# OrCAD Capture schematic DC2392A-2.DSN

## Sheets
1 PAGE2: size A; title: HIGH VOLTAGE SWITCHING SURGE STOPPER; rev: 2; company: TM
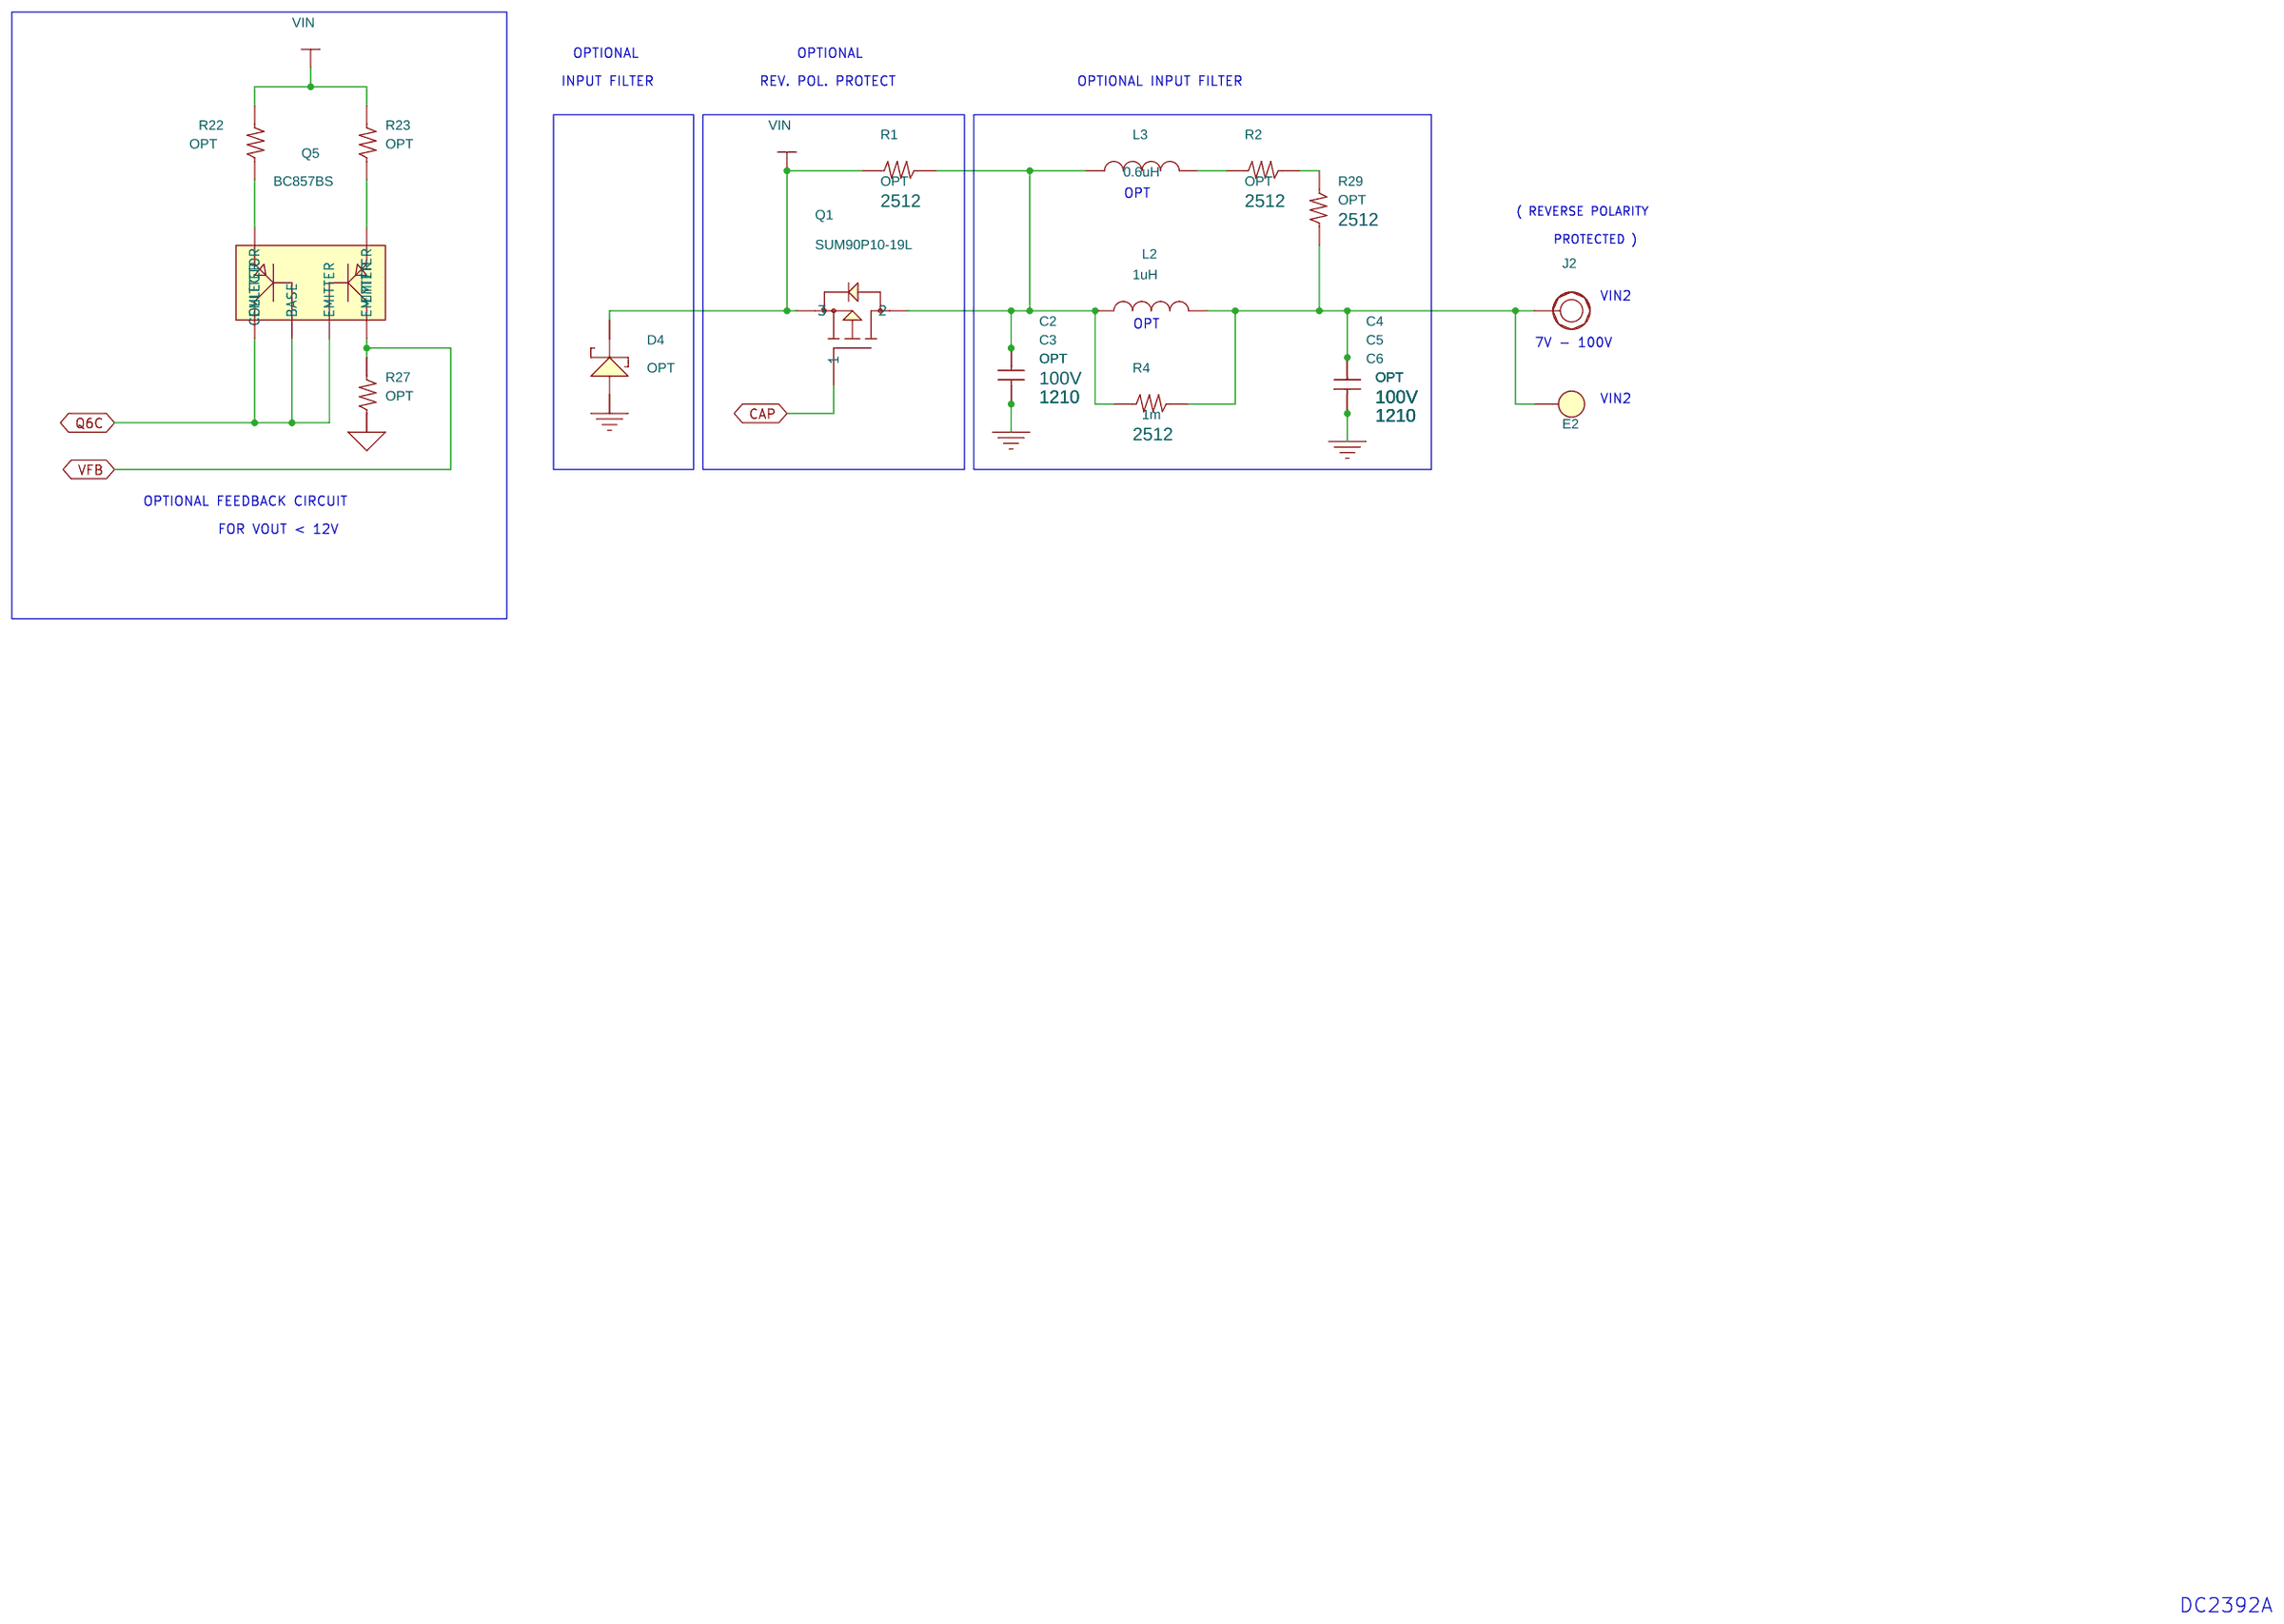
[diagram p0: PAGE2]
2 LTC7860EMSE: size Custom
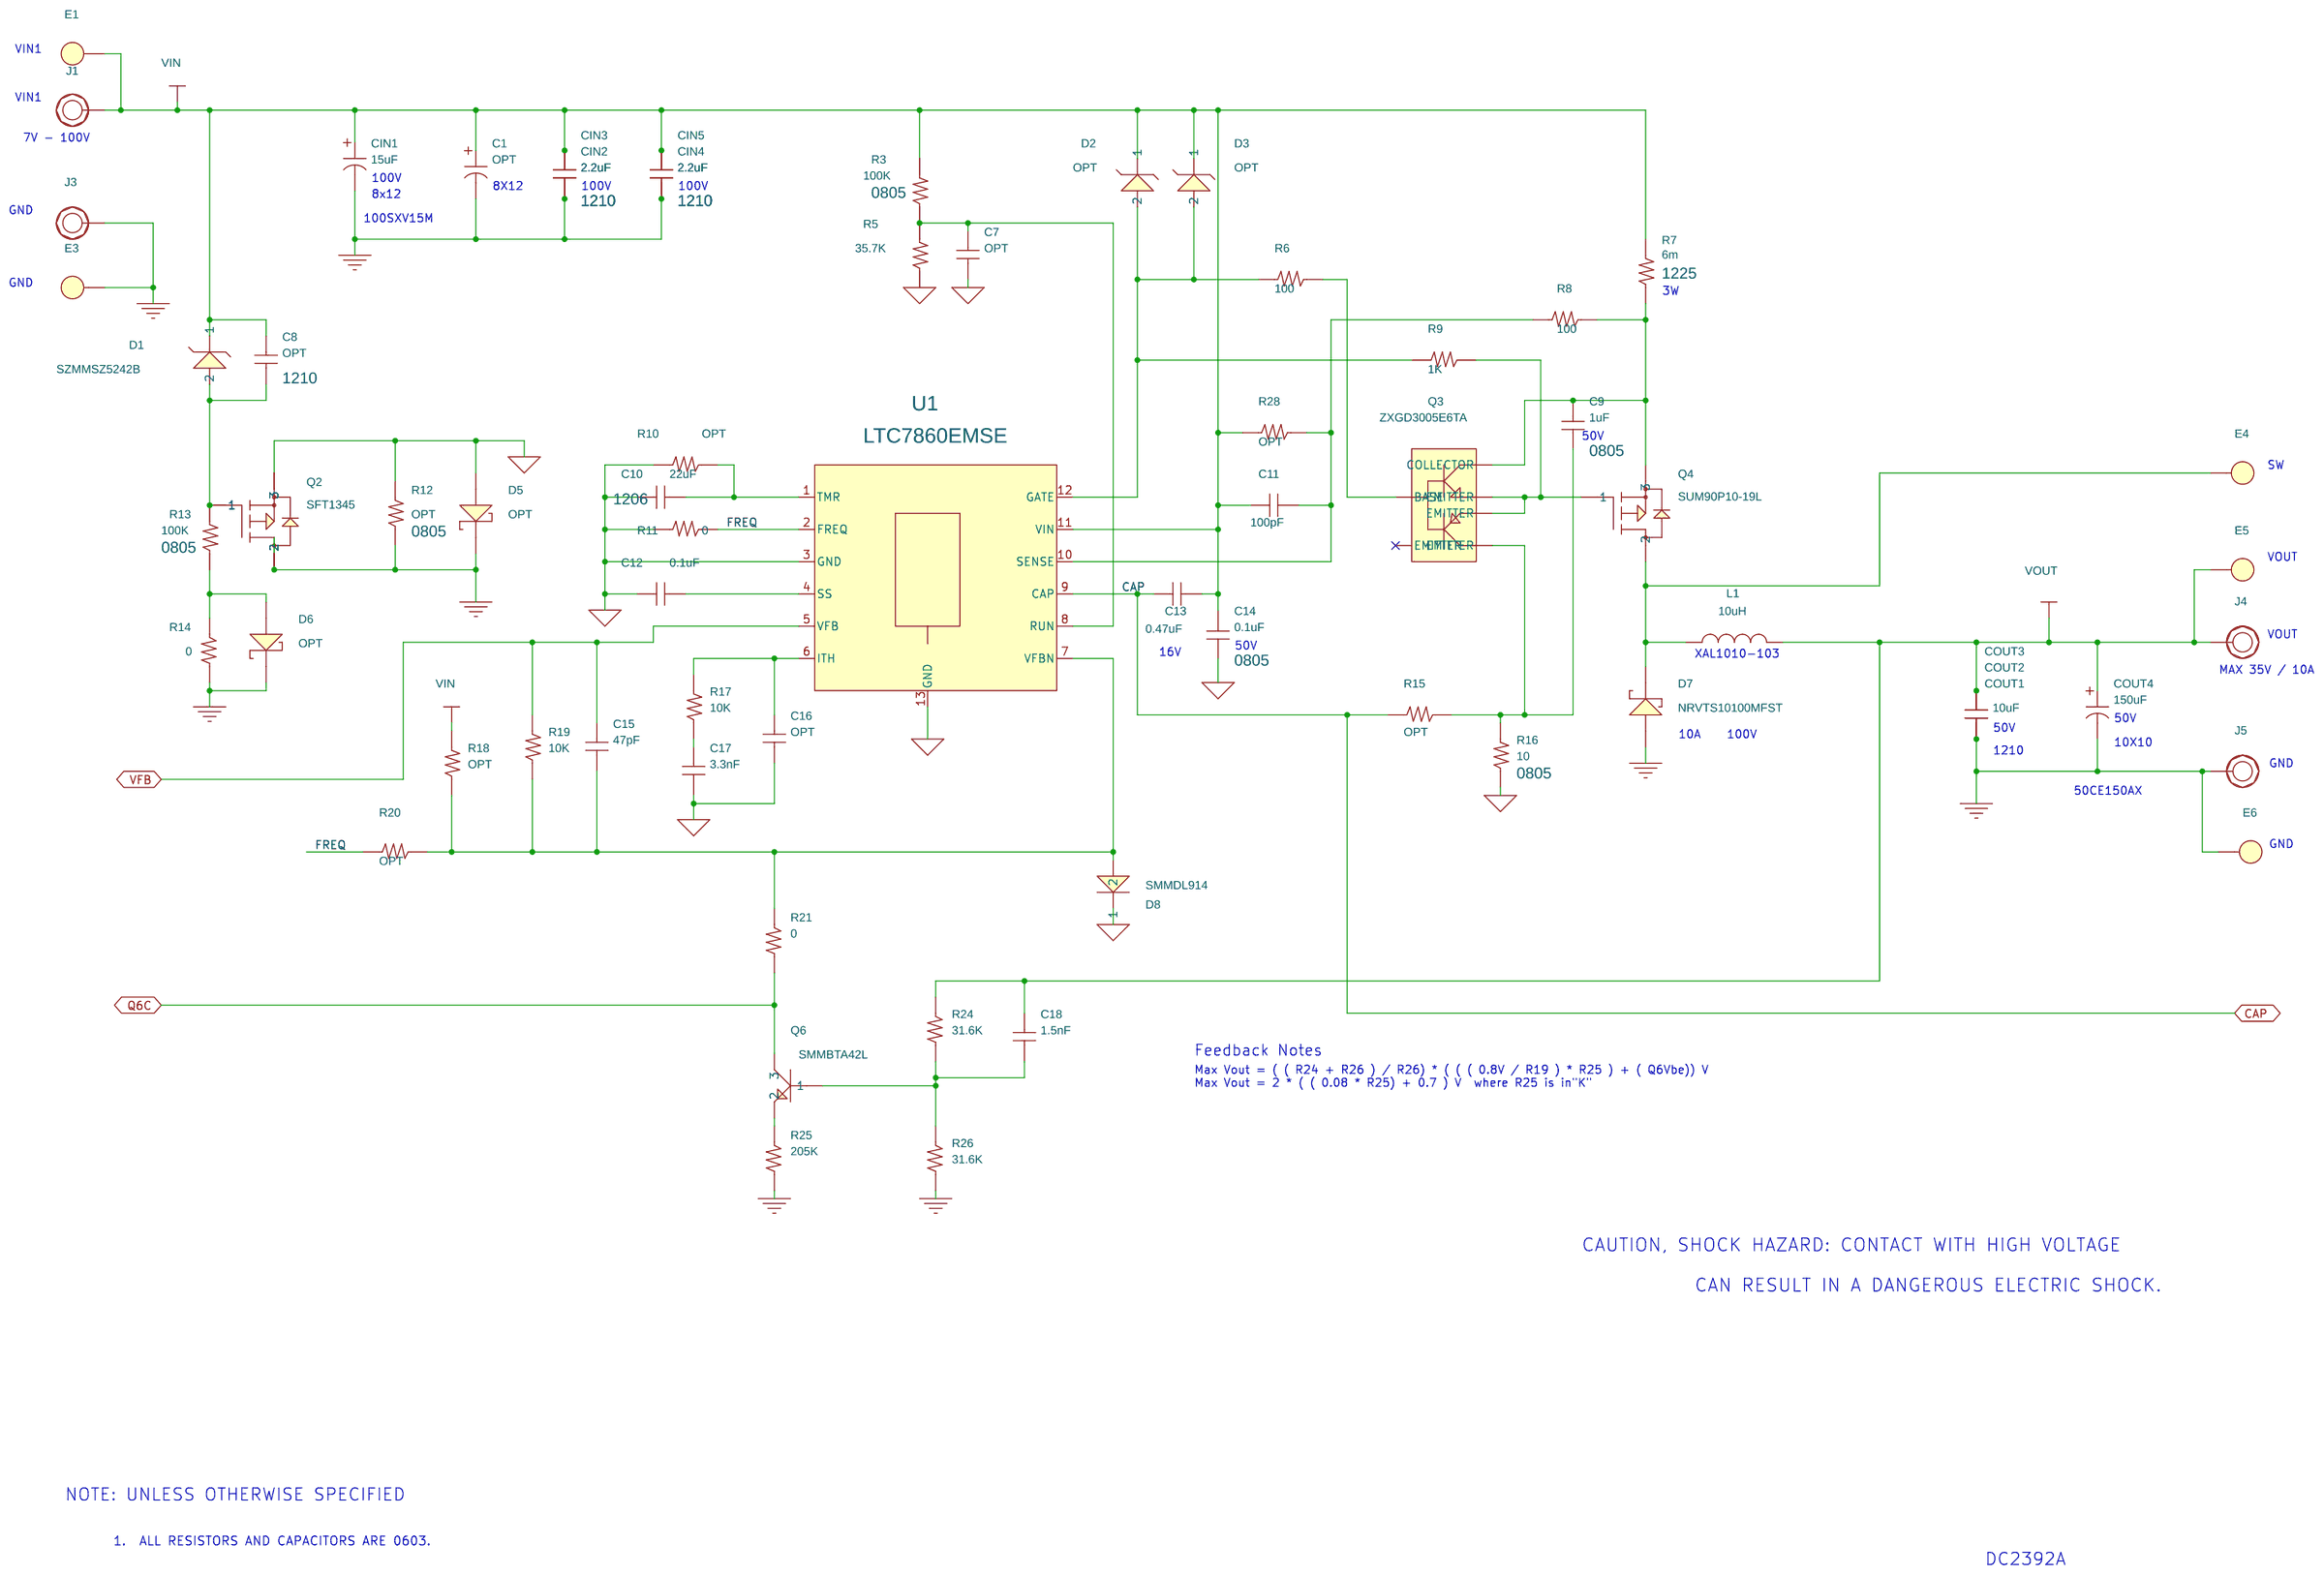
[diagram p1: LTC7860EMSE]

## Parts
sheet LTC7860EMSE
C1  OPT  [CAP-E12-8X12]
C7  OPT  [0603]
C8  OPT  [1210]
C9  1uF  [0805]
C10  22uF  [1206]
C11  100pF  [0603]
C12  0.1uF  [0603]
C13  0.47uF  [0603]
C14  0.1uF  [0805]
C15  47pF  [0603]
C16  OPT  [0603]
C17  3.3nF  [0603]
C18  1.5nF  [0603]
CIN1  15uF  [CAP-E12-8X12]
CIN2  2.2uF  [1210]
CIN3  2.2uF  [1210]
CIN4  2.2uF  [1210]
CIN5  2.2uF  [1210]
COUT1  10uF  [1206]
COUT2  10uF  [1206]
COUT3  10uF  [1206]
COUT4  150uF  [C-HVH-10X10.5]
D1  SZMMSZ5242B  [SOD123]
D2  OPT  [SOD123]
D3  OPT  [SOD123]
D5  OPT  [SOD123]
D6  OPT  [SOD323]
D7  NRVTS10100MFST  [DFN5-SO-8FL]
D8  SMMDL914  [SOD323]
E1  E_0  [TP\MMX\2501-2]
E3  E_0  [TP\MMX\2501-2]
E4  E_0  [TP\MMX\2501-2]
E5  E_0  [TP\MMX\2501-2]
E6  E_0  [TP\MMX\2501-2]
J1  Banana Jack  [KEYSTONE-575-4]
J3  Banana Jack  [KEYSTONE-575-4]
J4  Banana Jack  [KEYSTONE-575-4]
J5  Banana Jack  [KEYSTONE-575-4]
L1  10uH  [IND-XAL1010-103ME]
Q2  SFT1345  [TO-252]
Q3  ZXGD3005E6TA  [SOT23-6]
Q4  SUM90P10-19L  [TO-263AB]
Q6  SMMBTA42L  [SOT23]
R3  100K  [0805]
R5  35.7K  [0603]
R6  100  [0603]
R7  6m  [1225]
R8  100  [0603]
R9  1K  [0603]
R10  OPT  [0603]
R11  0  [0603]
R12  OPT  [0805]
R13  100K  [0805]
R14  0  [0603]
R15  OPT  [0603]
R16  10  [0805]
R17  10K  [0603]
R18  OPT  [0603]
R19  10K  [0603]
R20  OPT  [0603]
R21  0  [0603]
R24  31.6K  [0603]
R25  205K  [0603]
R26  31.6K  [0603]
R28  OPT  [0603]
U1  LTC7860EMSE  [MSE12]
sheet PAGE2
C2  OPT  [1210]
C3  OPT  [1210]
C4  OPT  [1210]
C5  OPT  [1210]
C6  OPT  [1210]
D4  OPT  [DFN5-SO-8FL]
E2  E_0  [TP\MMX\2501-2]
J2  Banana Jack  [KEYSTONE-575-4]
L2  1uH  [IND-XAL1010-103ME]
L3  0.6uH  [IND-XAL7030]
Q1  SUM90P10-19L  [TO-263AB]
Q5  BC857BS  [SOT363]
R1  OPT  [2512]
R2  OPT  [2512]
R4  1m  [2512]
R22  OPT  [0603]
R23  OPT  [0603]
R27  OPT  [0603]
R29  OPT  [2512]

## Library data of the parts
C1 CIN1 COUT4 = CAP
C7-C18 CIN2-CIN5 COUT1-COUT3 = CAP-NP
D1 = DIODE-ZENER_2_1
D2 = DIODE-ZENER_2
D3 = DIODE-ZENER_2_2
D4-D7 = DIODE_SCHOTTKY_1: DIODE, OPTION; Part Number: OPTION
D8 = DIODE-CMMR1U-SOD123F_0
E1-E6 = E_0: TURRET; Part Number: MILL MAX 2501-2-00-80-00-00-07-0
J1-J5 = E-KEY-575_0
L1-L3 = INDUCTOR
Q2 = MOSFET_P-DIODE_1_1
Q3 = NPN_2
Q1 Q4 = MOSFET_P-DIODE_1
Q6 = NPN-SOT223_6
R3 R5 R12 R13 R16-R20 R22-R24 R26-R28 = R
R1 R2 R4 R6-R11 R14 R15 R21 R25 R29 = R: V: 1%
U1 = LTC3863EMSE-MSE12_1
C2-C6 = CAP-NP: VOLTAGE: 100V
Q5 = PNP_2

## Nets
GND: C1.2 C2.2 C3.2 C4.2 C5.2 C6.2 CIN1.2 CIN2.2 CIN3.2 CIN4.2 CIN5.2 COUT1.2 COUT2.2 COUT3.2 COUT4.2 D4.2 D5.1 D6.1 D7.2 E3.1(A) E6.1(A) J3.1 J5.1 Q2.2 R12.1 R14.2 R25.2 R26.2
GND_SIGNAL: C7.2 C10.1 C12.1 C14.1 C16.2 C17.2 D5.2 D8.1 Q2.3 R5.1 R10.2 R11.2 R12.2 R16.1 R27.1 U1.3(GND) U1.13(GND)
VIN: C1.1 C8.1 C11.1 C13.2 C14.2 CIN1.1 CIN2.1 CIN3.1 CIN4.1 CIN5.1 D1.1 D2.1 D3.1 D4.1 E1.1(A) J1.1 Q1.3 R1.2 R3.2 R7.2 R18.2 R22.2 R23.2 R28.2 U1.11(VIN)
CAP: C13.1 Q1.1 R15.2 U1.9(CAP)
FREQ: R11.1 R20.2 U1.2(FREQ)
Q6C: Q5.2(BASE) Q5.5(EMITTER) Q5.6(EMITTER) Q6.3 R21.2
VFB: C15.1 Q5.3(EMITTER) R19.2 R27.2 U1.5(VFB)
VOUT: C18.1 COUT1.1 COUT2.1 COUT3.1 COUT4.1 E5.1(A) J4.1 L1.2 R24.1
N16958435: C11.2 R8.2 R28.1 U1.10(SENSE)
N16980078: C16.1 R17.2 U1.6(ITH)
N16980486: C17.1 R17.1
N16984781: C7.1 R3.1 R5.2 U1.8(RUN)
N16988700: C15.2 D8.2 R18.1 R19.1 R20.1 R21.1 U1.7(VFBN)
N17107621: D2.2 D3.2 R6.2 R9.2 U1.12(GATE)
N17230415: C10.2 R10.1 U1.1(TMR)
N17247637: C9.2 Q3.1(COLLECTOR) Q4.3 R7.1 R8.1
N17257498: C18.2 Q6.1 R24.2 R26.1
N17258066: Q6.2 R25.1
N17328730: C8.2 D1.2 Q2.1 R13.2
N17387128: C12.2 U1.4(SS)
N17419097: D7.1 E4.1(A) L1.1 Q4.2
N17476207: C9.1 Q3.3(EMITTER) R15.1 R16.2
N17476901: Q3.2(BASE) R6.1
N17486590: Q3.4(EMITTER) Q3.6(EMITTER) Q4.1 R9.1
N17494764: D6.2 R13.1 R14.1
N17507296: Q5.1(COLLECTOR) R22.1
N17507298: Q5.4(EMITTER) R23.1
N17508355: C4.1 C5.1 C6.1 E2.1(A) J2.1 L2.2 R4.1 R29.2
N17508390: R2.1 R29.1
N17508452: C2.1 C3.1 L2.1 L3.1 Q1.2 R1.1 R4.2
N17508512: L3.2 R2.2

Not connected (* = marked no-connect by the designer): Q3 5(EMITTER)*

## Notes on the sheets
sheet 1
- OPTIONAL
- OPTIONAL
- INPUT FILTER
- REV. POL. PROTECT
- OPTIONAL INPUT FILTER
- OPT
- ( REVERSE POLARITY
- PROTECTED )
- VIN2
- OPT
- 7V - 100V
- VIN2
- OPTIONAL FEEDBACK CIRCUIT
- FOR VOUT < 12V
- DC2392A
sheet 2
- VIN1
- VIN1
- 7V - 100V
- 100V
- 8X12
- 100V
- 100V
- 8x12
- GND
- 100SXV15M
- GND
- 3W
- 50V
- SW
- VOUT
- VOUT
- 16V
- 50V
- XAL1010-103
- MAX 35V / 10A
- 50V
- 10A
- 100V
- 50V
- 1210
- 10X10
- GND
- 50CE150AX
- GND
- Feedback Notes
- Max Vout = ( ( R24 + R26 ) / R26) * ( ( ( 0.8V / R19 ) * R25 ) + ( Q6Vbe)) V
  Max Vout = 2 * ( ( 0.08 * R25) + 0.7 ) V  where R25 is in"K"
- CAUTION, SHOCK HAZARD: CONTACT WITH HIGH VOLTAGE
- CAN RESULT IN A DANGEROUS ELECTRIC SHOCK.
- NOTE: UNLESS OTHERWISE SPECIFIED
- 1.  ALL RESISTORS AND CAPACITORS ARE 0603.
- DC2392A
